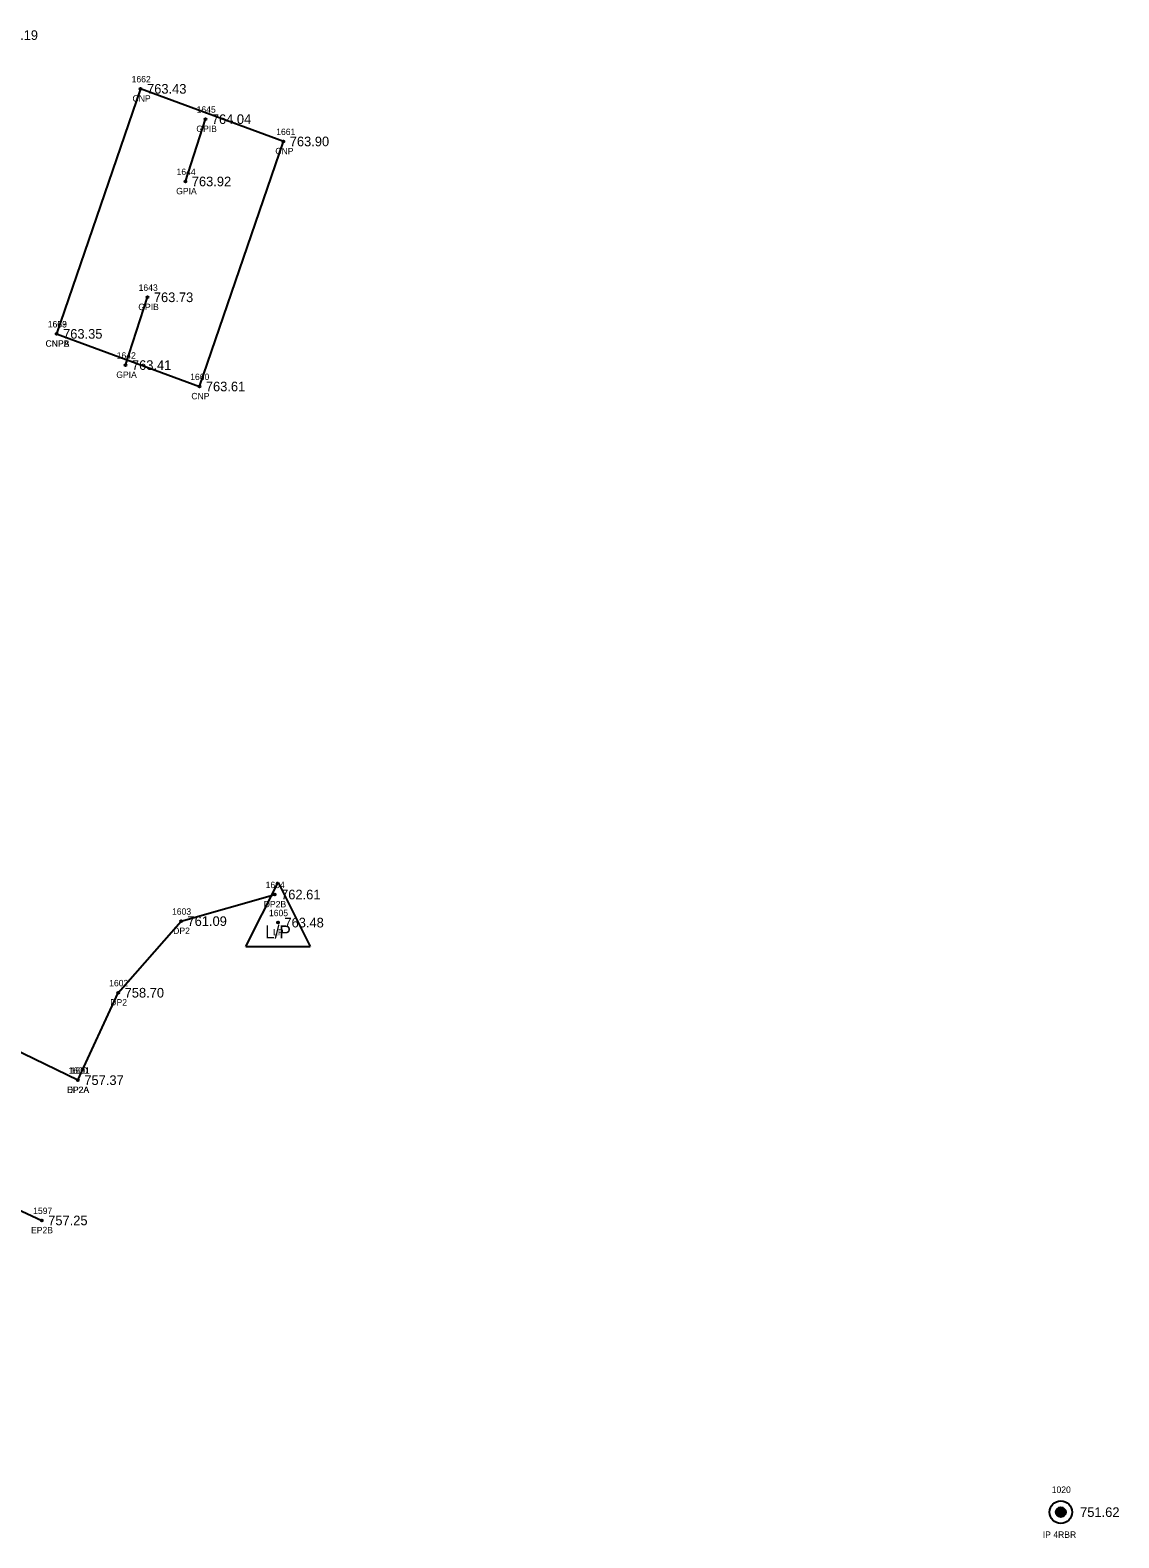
# Model space of a CAD drawing. Extents: x 1736563 to 1738032, y 1150548 to 1154248.
# Drawn here: x 1737797.6 to 1737967.2, y 1153394.6 to 1153629.4 of the extents above; entities that cross this region are included whole.
import ezdxf

# ---------------------------------------------------------------- set-up
doc = ezdxf.new("R2010")
doc.units = 0
for name, color, linetype in [('RD_EX_BldgApp', 7, 'Continuous'), ('RD_EX_BldgApp_txCode', 7, 'Continuous'), ('RD_EX_Driveway', 7, 'Continuous'), ('RD_EX_Driveway_txCode', 7, 'Continuous'), ('RD_EX_DV_Prop_txCode', 7, 'Continuous'), ('RD_EX_DV_PropPin', 7, 'Continuous'), ('RD_EX_Road', 7, 'Continuous'), ('RD_EX_Road_txCode', 7, 'Continuous'), ('RD_EX_TX_BldgApp_ELEV', 7, 'Continuous'), ('RD_EX_TX_Driveway_ELEV', 7, 'Continuous'), ('RD_EX_TX_DV_Prop_ELEV', 7, 'Continuous'), ('RD_EX_TX_Road_ELEV', 7, 'Continuous'), ('RD_EX_TX_UT_ELEV', 7, 'Continuous'), ('RD_EX_UT', 7, 'Continuous'), ('RD_EX_UT_txCode', 7, 'Continuous'), ('RD_SMD_Locator', 7, 'Continuous')]:
    doc.layers.add(name, color=color, linetype=linetype)

msp = doc.modelspace()

# ---------------------------------------------------------------- linework, layer by layer
at = {"layer": 'RD_EX_BldgApp'}
for p, q in [((1737821.82, 1153605.83), (1737824.94, 1153615.53)), ((1737812.5, 1153577.23), (1737815.91, 1153587.79))]:
    msp.add_line(p, q, dxfattribs=at)
msp.add_lwpolyline([(1737801.77, 1153582.09), (1737824.01, 1153573.9), (1737837.08, 1153612.06), (1737814.85, 1153620.25), (1737801.77, 1153582.09)], dxfattribs=at)
at = {"layer": 'RD_EX_Driveway'}
msp.add_lwpolyline([(1737805.08, 1153465.87), (1737811.36, 1153479.49), (1737821.15, 1153490.64), (1737835.73, 1153494.78)], dxfattribs=at)
at = {"layer": 'RD_EX_DV_PropPin'}
for p, q in [((1737957.46, 1153398.4), (1737957.46, 1153398.8)), ((1737957.49, 1153398.3), (1737957.49, 1153398.9)), ((1737957.53, 1153398.23), (1737957.53, 1153398.97)), ((1737957.56, 1153398.17), (1737957.56, 1153399.03)), ((1737957.6, 1153398.13), (1737957.6, 1153399.07)), ((1737957.63, 1153398.09), (1737957.63, 1153399.12)), ((1737957.67, 1153398.05), (1737957.67, 1153399.15)), ((1737957.7, 1153398.02), (1737957.7, 1153399.18)), ((1737957.74, 1153397.99), (1737957.74, 1153399.21)), ((1737957.77, 1153397.97), (1737957.77, 1153399.23)), ((1737957.81, 1153397.94), (1737957.81, 1153399.26)), ((1737957.84, 1153397.92), (1737957.84, 1153399.28)), ((1737957.88, 1153397.91), (1737957.88, 1153399.29)), ((1737957.91, 1153397.89), (1737957.91, 1153399.31)), ((1737957.95, 1153397.88), (1737957.95, 1153399.32)), ((1737957.98, 1153397.87), (1737957.98, 1153399.33)), ((1737958.02, 1153397.86), (1737958.02, 1153399.34)), ((1737958.05, 1153397.85), (1737958.05, 1153399.35)), ((1737958.09, 1153397.85), (1737958.09, 1153399.35)), ((1737958.12, 1153397.84), (1737958.12, 1153399.36)), ((1737958.16, 1153397.84), (1737958.16, 1153399.36)), ((1737958.19, 1153397.84), (1737958.19, 1153399.36)), ((1737958.23, 1153397.84), (1737958.23, 1153399.36)), ((1737958.26, 1153397.84), (1737958.26, 1153399.36)), ((1737958.3, 1153397.85), (1737958.3, 1153399.35)), ((1737958.33, 1153397.85), (1737958.33, 1153399.35)), ((1737958.37, 1153397.86), (1737958.37, 1153399.34)), ((1737958.4, 1153397.87), (1737958.4, 1153399.33)), ((1737958.44, 1153397.88), (1737958.44, 1153399.32)), ((1737958.47, 1153397.89), (1737958.47, 1153399.31)), ((1737958.51, 1153397.91), (1737958.51, 1153399.29)), ((1737958.54, 1153397.92), (1737958.54, 1153399.28)), ((1737958.58, 1153397.94), (1737958.58, 1153399.26)), ((1737958.61, 1153397.97), (1737958.61, 1153399.23)), ((1737958.65, 1153397.99), (1737958.65, 1153399.21)), ((1737958.68, 1153398.02), (1737958.68, 1153399.18)), ((1737958.72, 1153398.05), (1737958.72, 1153399.15)), ((1737958.75, 1153398.09), (1737958.75, 1153399.12)), ((1737958.79, 1153398.13), (1737958.79, 1153399.07)), ((1737958.82, 1153398.17), (1737958.82, 1153399.03)), ((1737958.86, 1153398.23), (1737958.86, 1153398.97)), ((1737958.89, 1153398.3), (1737958.89, 1153398.9)), ((1737958.93, 1153398.4), (1737958.93, 1153398.8))]:
    msp.add_line(p, q, dxfattribs=at)
for radius in [1.75, 0.761]:
    msp.add_circle((1737958.19, 1153398.6), radius, dxfattribs=at)
at = {"layer": 'RD_EX_Road'}
for points in [[(1737805.08, 1153465.87), (1737774.5, 1153480.68), (1737739.67, 1153495.73), (1737733.68, 1153500.14), (1737729.79, 1153505.37), (1737725.08, 1153513.79)], [(1737705.88, 1153458.65), (1737721.44, 1153470.54), (1737736.82, 1153470.58), (1737746.44, 1153467.95), (1737764.24, 1153460.43), (1737799.45, 1153444.03)]]:
    msp.add_lwpolyline(points, dxfattribs=at)
at = {"layer": 'RD_EX_UT'}
for p, q in [((1737831.25, 1153486.68), (1737836.25, 1153496.68)), ((1737836.25, 1153496.68), (1737841.25, 1153486.68)), ((1737831.25, 1153486.68), (1737841.25, 1153486.68))]:
    msp.add_line(p, q, dxfattribs=at)
at = {"layer": 'RD_SMD_Locator'}
for centre in [(1737814.85, 1153620.25), (1737824.94, 1153615.53), (1737837.08, 1153612.06), (1737821.82, 1153605.83), (1737815.91, 1153587.79), (1737801.77, 1153582.09), (1737801.77, 1153582.09), (1737812.5, 1153577.23), (1737824.01, 1153573.9), (1737835.73, 1153494.78), (1737821.15, 1153490.64), (1737836.25, 1153490.41), (1737811.36, 1153479.49), (1737805.08, 1153465.87), (1737805.08, 1153465.87), (1737799.45, 1153444.03), (1737958.19, 1153398.6)]:
    msp.add_circle(centre, 0.15, dxfattribs=at)

# ---------------------------------------------------------------- texts
at = {"layer": 'RD_EX_BldgApp_txCode'}
for s, p in [('1662', (1737813.45, 1153621.25)), ('CNP', (1737813.59, 1153618.25)), ('1645', (1737823.57, 1153616.53)), ('GPIB', (1737823.53, 1153613.53)), ('1661', (1737835.97, 1153613.06)), ('CNP', (1737835.83, 1153610.06)), ('1644', (1737820.45, 1153606.83)), ('GPIA', (1737820.39, 1153603.83)), ('1643', (1737814.54, 1153588.79)), ('GPIB', (1737814.49, 1153585.79)), ('1663', (1737800.38, 1153583.09)), ('1659', (1737800.4, 1153583.09)), ('CNPA', (1737800.03, 1153580.09)), ('CNPB', (1737800.05, 1153580.09)), ('1642', (1737811.13, 1153578.23)), ('GPIA', (1737811.06, 1153575.23)), ('1660', (1737822.57, 1153574.9)), ('CNP', (1737822.75, 1153571.9))]:
    msp.add_text(s, height=1, dxfattribs=at).set_placement(p)
at = {"layer": 'RD_EX_Driveway_txCode'}
for s, p in [('1604', (1737834.32, 1153495.78)), ('DP2B', (1737834.03, 1153492.78)), ('1603', (1737819.74, 1153491.64)), ('DP2', (1737819.92, 1153488.64)), ('1602', (1737809.95, 1153480.49)), ('DP2', (1737810.13, 1153477.49)), ('1601', (1737803.95, 1153466.87)), ('DP2A', (1737803.36, 1153463.87))]:
    msp.add_text(s, height=1, dxfattribs=at).set_placement(p)
at = {"layer": 'RD_EX_DV_Prop_txCode'}
for s, p in [('1020', (1737956.77, 1153401.6)), ('IP 4RBR', (1737955.38, 1153394.6))]:
    msp.add_text(s, height=1, dxfattribs=at).set_placement(p)
at = {"layer": 'RD_EX_Road_txCode'}
for s, p in [('1600', (1737803.63, 1153466.87)), ('EP2A', (1737803.39, 1153463.87)), ('1597', (1737798.11, 1153445.03)), ('EP2B', (1737797.78, 1153442.03))]:
    msp.add_text(s, height=1, dxfattribs=at).set_placement(p)
at = {"layer": 'RD_EX_TX_BldgApp_ELEV'}
for s, p in [('763.43', (1737815.85, 1153619.5)), ('764.04', (1737825.94, 1153614.78)), ('763.90', (1737838.08, 1153611.31)), ('763.92', (1737822.82, 1153605.08)), ('763.73', (1737816.91, 1153587.04)), ('763.35', (1737802.77, 1153581.34)), ('763.35', (1737802.77, 1153581.34)), ('763.41', (1737813.5, 1153576.48)), ('763.61', (1737825.01, 1153573.15))]:
    msp.add_text(s, height=1.5, dxfattribs=at).set_placement(p)
at = {"layer": 'RD_EX_TX_Driveway_ELEV'}
for s, p in [('765.19', (1737792.73, 1153627.87)), ('762.61', (1737836.73, 1153494.03)), ('761.09', (1737822.15, 1153489.89)), ('758.70', (1737812.36, 1153478.74)), ('757.37', (1737806.08, 1153465.12))]:
    msp.add_text(s, height=1.5, dxfattribs=at).set_placement(p)
at = {"layer": 'RD_EX_TX_DV_Prop_ELEV'}
msp.add_text('751.62', height=1.5, dxfattribs=at).set_placement((1737961.19, 1153397.85))
at = {"layer": 'RD_EX_TX_Road_ELEV'}
for s, p in [('757.37', (1737806.08, 1153465.12)), ('757.25', (1737800.45, 1153443.28))]:
    msp.add_text(s, height=1.5, dxfattribs=at).set_placement(p)
at = {"layer": 'RD_EX_TX_UT_ELEV'}
msp.add_text('763.48', height=1.5, dxfattribs=at).set_placement((1737837.25, 1153489.66))
at = {"layer": 'RD_EX_UT'}
msp.add_text('L/P', height=2, dxfattribs=at).set_placement((1737834.24, 1153487.96))
at = {"layer": 'RD_EX_UT_txCode'}
for s, p in [('1605', (1737834.84, 1153491.41)), ('LP', (1737835.49, 1153488.41))]:
    msp.add_text(s, height=1, dxfattribs=at).set_placement(p)

doc.saveas('drawing.dxf')
